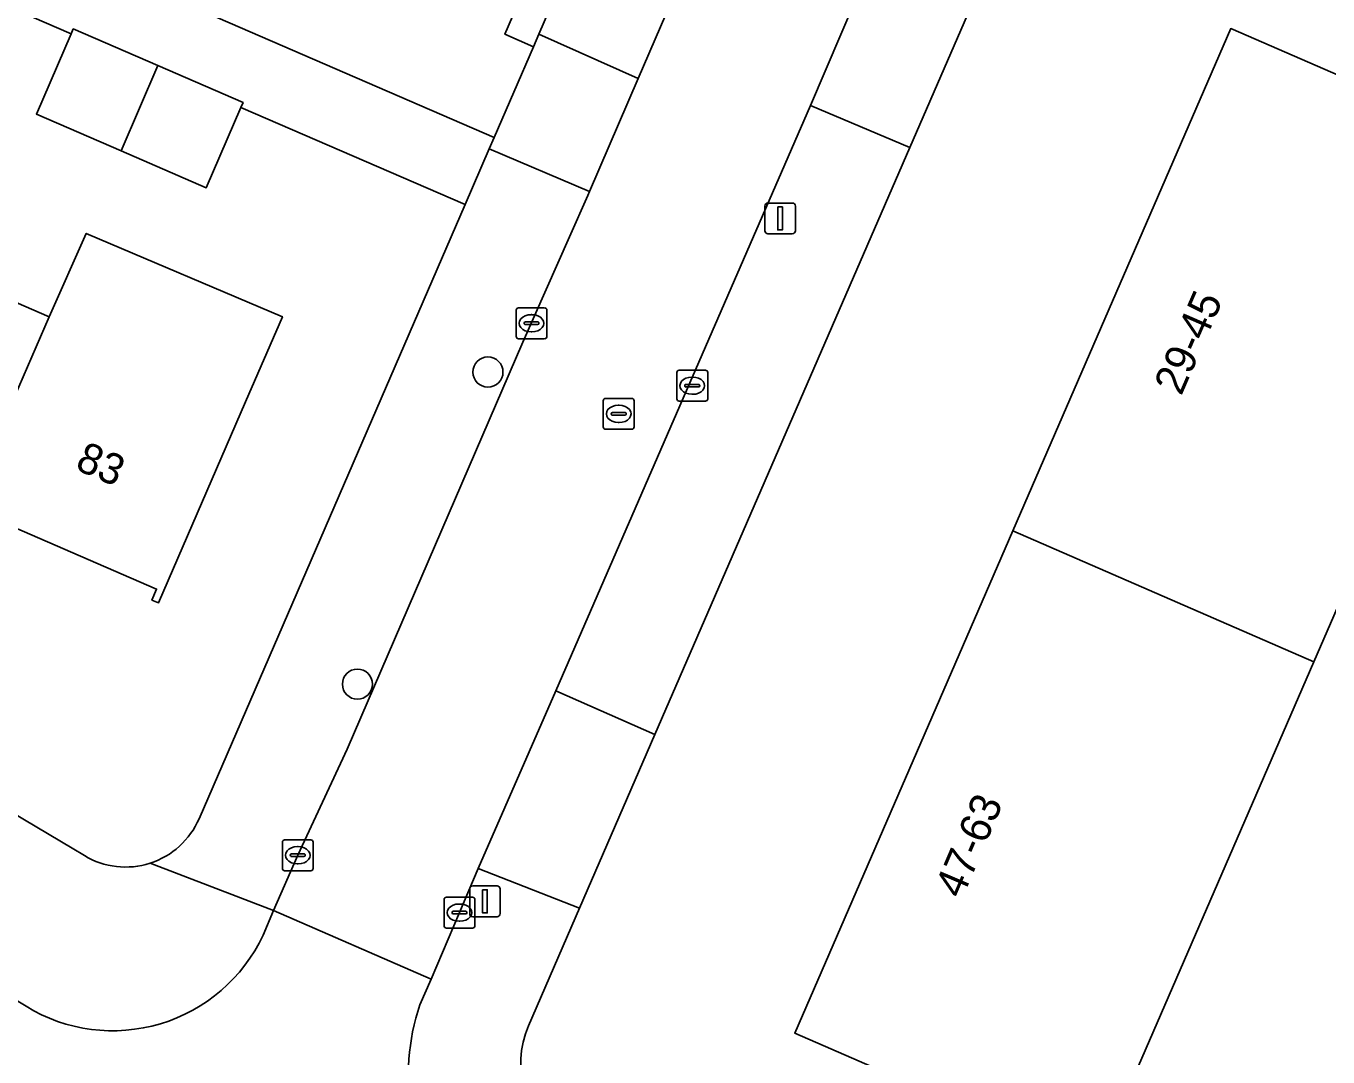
# Model space of a CAD drawing. Extents: x 162803 to 163818, y 381639 to 382475.
# Drawn here: x 163434.73 to 163477.02, y 381804.92 to 381838.38 of the extents above; entities that cross this region are included whole.
import ezdxf

# ---------------------------------------------------------------- set-up
doc = ezdxf.new("R2010")
doc.units = 0
for name, color, linetype in [('IMGEO_Boom', 7, 'Continuous'), ('IMGEO_Erf', 7, 'Continuous'), ('IMGEO_Groenvoorziening', 7, 'Continuous'), ('IMGEO_Kolk', 7, 'Continuous'), ('IMGEO_Lichtmast', 7, 'Continuous'), ('IMGEO_Pand', 7, 'Continuous'), ('IMGEO_Pand_nummerreeks', 7, 'Continuous'), ('IMGEO_Rijbaan_lokaal_gesloten', 7, 'Continuous'), ('IMGEO_Rijbaan_lokaal_open', 7, 'Continuous'), ('IMGEO_Rioolput', 7, 'Continuous'), ('IMGEO_Voetpad_open', 7, 'Continuous')]:
    doc.layers.add(name, color=color, linetype=linetype)

msp = doc.modelspace()

# ---------------------------------------------------------------- linework, layer by layer
at = {"layer": 'IMGEO_Boom'}
for centre in [(163449.734, 381827.148), (163445.496, 381817.017)]:
    msp.add_circle(centre, 0.489, dxfattribs=at)
at = {"layer": 'IMGEO_Erf'}
for points in [[(163436.198, 381838.123), (163434.517, 381838.854), (163432.723, 381839.632), (163429.378, 381841.081), (163428.109, 381838.155), (163425.245, 381839.398), (163425.173, 381839.429), (163422.236, 381840.702), (163423.504, 381843.626), (163420.299, 381845.015), (163413.989, 381847.548), (163416.807, 381846.326), (163415.568, 381843.47), (163412.751, 381844.692), (163412.199, 381843.419), (163405.84, 381846.176), (163407.63, 381850.305), (163403.019, 381852.311), (163395.819, 381835.705), (163436.629, 381811.45)], [(163467.165, 381843.034), (163465.988, 381840.322), (163463.432, 381834.438), (163455.158, 381815.381), (163452.711, 381809.747), (163451.053, 381805.927)], [(163440.352, 381812.65), (163448.992, 381832.592), (163441.712, 381835.735), (163440.584, 381833.133), (163437.818, 381834.332), (163435.07, 381835.523), (163436.198, 381838.123)], [(163429.266, 381831.638), (163435.482, 381828.943), (163436.691, 381831.651), (163443.06, 381828.944), (163441.861, 381826.178), (163439.032, 381819.653), (163438.82, 381819.745), (163438.975, 381820.104), (163432.952, 381822.703)]]:
    msp.add_lwpolyline(points, dxfattribs=at)
msp.add_lwpolyline([(163469.482, 381801.434), (163459.697, 381805.683), (163466.777, 381821.989), (163473.858, 381838.296), (163483.642, 381834.047), (163476.562, 381817.741)], close=True, dxfattribs=at)
for centre, radius, start, end in [((163437.966, 381813.676), 2.597, 287.8731, 336.7317), ((163437.967, 381813.675), 2.596, 238.9884, 287.8599), ((163453.778, 381804.734), 2.975, 156.3447, 240.6795)]:
    msp.add_arc(centre, radius, start, end, dxfattribs=at)
at = {"layer": 'IMGEO_Groenvoorziening'}
for points in [[(163455.817, 381848.343), (163454.888, 381848.734), (163454.325, 381847.435), (163450.286, 381838.112), (163451.209, 381837.708), (163451.387, 381838.119)], [(163435.32, 381840.713), (163434.517, 381838.854), (163436.198, 381838.123), (163436.268, 381838.286), (163439.015, 381837.095), (163441.782, 381835.896), (163441.712, 381835.735), (163448.992, 381832.592), (163449.775, 381834.399), (163449.934, 381834.765), (163435.46, 381841.037)]]:
    msp.add_lwpolyline(points, close=True, dxfattribs=at)
at = {"layer": 'IMGEO_Kolk'}
for p, q in [((163450.65, 381828.305), (163450.65, 381829.157)), ((163450.725, 381829.231), (163451.577, 381829.231)), ((163451.651, 381829.157), (163451.651, 381828.305)), ((163450.909, 381828.725), (163450.909, 381828.737)), ((163450.952, 381828.774), (163451.35, 381828.774)), ((163451.138, 381829.011), (163451.163, 381829.011)), ((163451.393, 381828.737), (163451.393, 381828.725)), ((163451.347, 381828.688), (163450.949, 381828.688)), ((163451.161, 381828.451), (163451.136, 381828.451)), ((163451.577, 381828.231), (163450.725, 381828.231)), ((163455.87, 381826.28), (163455.87, 381827.132)), ((163455.945, 381827.206), (163456.797, 381827.206)), ((163456.871, 381827.132), (163456.871, 381826.28)), ((163456.129, 381826.7), (163456.129, 381826.712)), ((163456.567, 381826.663), (163456.169, 381826.663)), ((163456.172, 381826.749), (163456.57, 381826.749)), ((163456.358, 381826.986), (163456.383, 381826.986)), ((163456.613, 381826.712), (163456.613, 381826.7)), ((163456.797, 381826.206), (163455.945, 381826.206)), ((163456.381, 381826.426), (163456.356, 381826.426)), ((163443.058, 381811.036), (163443.058, 381811.888)), ((163443.133, 381811.962), (163443.985, 381811.962)), ((163444.059, 381811.888), (163444.059, 381811.036)), ((163443.317, 381811.456), (163443.317, 381811.468)), ((163443.755, 381811.419), (163443.357, 381811.419)), ((163443.36, 381811.505), (163443.758, 381811.505)), ((163443.546, 381811.742), (163443.571, 381811.742)), ((163443.801, 381811.468), (163443.801, 381811.456)), ((163443.985, 381810.962), (163443.133, 381810.962)), ((163443.569, 381811.182), (163443.544, 381811.182)), ((163448.385, 381810.1), (163449.237, 381810.1)), ((163448.31, 381809.174), (163448.31, 381810.026)), ((163448.798, 381809.88), (163448.823, 381809.88)), ((163449.311, 381810.026), (163449.311, 381809.174)), ((163448.569, 381809.594), (163448.569, 381809.606)), ((163449.007, 381809.557), (163448.609, 381809.557)), ((163448.612, 381809.643), (163449.01, 381809.643)), ((163448.821, 381809.32), (163448.796, 381809.32)), ((163449.053, 381809.606), (163449.053, 381809.594)), ((163449.237, 381809.1), (163448.385, 381809.1))]:
    msp.add_line(p, q, dxfattribs=at)
for points in [[(163450.65, 381828.305), (163450.65, 381829.157)], [(163450.725, 381829.231), (163451.577, 381829.231)], [(163451.651, 381829.157), (163451.651, 381828.305)], [(163451.577, 381828.231), (163450.725, 381828.231)], [(163455.87, 381826.28), (163455.87, 381827.132)], [(163455.945, 381827.206), (163456.797, 381827.206)], [(163456.871, 381827.132), (163456.871, 381826.28)], [(163456.797, 381826.206), (163455.945, 381826.206)], [(163443.058, 381811.036), (163443.058, 381811.888)], [(163443.133, 381811.962), (163443.985, 381811.962)], [(163444.059, 381811.888), (163444.059, 381811.036)], [(163443.985, 381810.962), (163443.133, 381810.962)], [(163448.385, 381810.1), (163449.237, 381810.1)], [(163448.31, 381809.174), (163448.31, 381810.026)], [(163449.311, 381810.026), (163449.311, 381809.174)], [(163449.237, 381809.1), (163448.385, 381809.1)]]:
    msp.add_lwpolyline(points, dxfattribs=at)
for centre, radius, start, end in [((163450.727, 381829.155), 0.0765, 91.552, 178.448), ((163450.727, 381829.155), 0.0765, 91.552, 178.448), ((163451.575, 381829.155), 0.0765, 1.552, 88.448), ((163451.575, 381829.155), 0.0765, 1.552, 88.448), ((163450.949, 381828.734), 0.0403, 85.8775, 175.7526), ((163450.946, 381828.724), 0.0366, 178.938, 274.7102), ((163451.35, 381828.731), 0.043, 264.8664, 352.4533), ((163451.354, 381828.736), 0.0386, 1.7309, 96.639), ((163450.727, 381828.307), 0.0765, 181.552, 268.448), ((163450.727, 381828.307), 0.0765, 181.552, 268.448), ((163451.575, 381828.307), 0.0765, 271.552, 358.448), ((163451.575, 381828.307), 0.0765, 271.552, 358.448), ((163455.947, 381827.13), 0.0765, 91.552, 178.448), ((163455.947, 381827.13), 0.0765, 91.552, 178.448), ((163456.795, 381827.13), 0.0765, 1.552, 88.448), ((163456.795, 381827.13), 0.0765, 1.552, 88.448), ((163456.169, 381826.709), 0.0403, 85.8775, 175.7526), ((163456.166, 381826.699), 0.0366, 178.938, 274.7102), ((163456.57, 381826.706), 0.043, 264.8664, 352.4533), ((163456.574, 381826.711), 0.0386, 1.7309, 96.639), ((163455.947, 381826.282), 0.0765, 181.552, 268.448), ((163455.947, 381826.282), 0.0765, 181.552, 268.448), ((163456.795, 381826.282), 0.0765, 271.552, 358.448), ((163456.795, 381826.282), 0.0765, 271.552, 358.448), ((163443.135, 381811.886), 0.0765, 91.552, 178.448), ((163443.135, 381811.886), 0.0765, 91.552, 178.448), ((163443.983, 381811.886), 0.0765, 1.552, 88.448), ((163443.983, 381811.886), 0.0765, 1.552, 88.448), ((163443.357, 381811.465), 0.0403, 85.8775, 175.7526), ((163443.354, 381811.455), 0.0366, 178.938, 274.7102), ((163443.758, 381811.462), 0.043, 264.8664, 352.4533), ((163443.762, 381811.467), 0.0386, 1.7309, 96.639), ((163443.135, 381811.038), 0.0765, 181.552, 268.448), ((163443.135, 381811.038), 0.0765, 181.552, 268.448), ((163443.983, 381811.038), 0.0765, 271.552, 358.448), ((163443.983, 381811.038), 0.0765, 271.552, 358.448), ((163448.387, 381810.024), 0.0765, 91.552, 178.448), ((163448.387, 381810.024), 0.0765, 91.552, 178.448), ((163449.235, 381810.024), 0.0765, 1.552, 88.448), ((163449.235, 381810.024), 0.0765, 1.552, 88.448), ((163448.609, 381809.603), 0.0403, 85.8775, 175.7526), ((163448.606, 381809.593), 0.0366, 178.938, 274.7102), ((163449.01, 381809.6), 0.043, 264.8664, 352.4533), ((163449.014, 381809.605), 0.0386, 1.7309, 96.639), ((163448.387, 381809.176), 0.0765, 181.552, 268.448), ((163448.387, 381809.176), 0.0765, 181.552, 268.448), ((163449.235, 381809.176), 0.0765, 271.552, 358.448), ((163449.235, 381809.176), 0.0765, 271.552, 358.448)]:
    msp.add_arc(centre, radius, start, end, dxfattribs=at)
for centre, major_axis, ratio, start_param, end_param in [((163451.137, 381828.731), (-0.387, 0.002), 0.722429, 4.712389, 7.853982), ((163451.162, 381828.731), (-0.39, 0.002), 0.717154, 1.570796, 4.712389), ((163456.357, 381826.706), (-0.387, 0.002), 0.722429, 4.712389, 7.853982), ((163456.382, 381826.706), (-0.39, 0.002), 0.717154, 1.570796, 4.712389), ((163443.545, 381811.462), (-0.387, 0.002), 0.722429, 4.712389, 7.853982), ((163443.57, 381811.462), (-0.39, 0.002), 0.717154, 1.570796, 4.712389), ((163448.797, 381809.6), (-0.387, 0.002), 0.722429, 4.712389, 7.853982), ((163448.822, 381809.6), (-0.39, 0.002), 0.717154, 1.570796, 4.712389)]:
    msp.add_ellipse(centre, major_axis=major_axis, ratio=ratio, start_param=start_param, end_param=end_param, dxfattribs=at)
at = {"layer": 'IMGEO_Lichtmast'}
for p, q in [((163458.729, 381831.735), (163458.729, 381832.535)), ((163458.729, 381832.535), (163458.729, 381831.735)), ((163458.829, 381832.635), (163459.619, 381832.635)), ((163459.619, 381832.635), (163458.829, 381832.635)), ((163459.719, 381832.535), (163459.719, 381831.735)), ((163459.719, 381831.735), (163459.719, 381832.535)), ((163459.619, 381831.635), (163458.829, 381831.635)), ((163458.829, 381831.635), (163459.619, 381831.635)), ((163449.143, 381809.568), (163449.143, 381810.368)), ((163449.143, 381810.368), (163449.143, 381809.568)), ((163449.243, 381810.468), (163450.033, 381810.468)), ((163450.033, 381810.468), (163449.243, 381810.468)), ((163450.133, 381810.368), (163450.133, 381809.568)), ((163450.133, 381809.568), (163450.133, 381810.368)), ((163450.033, 381809.468), (163449.243, 381809.468)), ((163449.243, 381809.468), (163450.033, 381809.468))]:
    msp.add_line(p, q, dxfattribs=at)
for points in [[(163459.149, 381832.51), (163459.299, 381832.51), (163459.299, 381831.76), (163459.149, 381831.76), (163459.149, 381832.51)], [(163449.563, 381810.343), (163449.713, 381810.343), (163449.713, 381809.593), (163449.563, 381809.593), (163449.563, 381810.343)]]:
    msp.add_lwpolyline(points, dxfattribs=at)
for centre, start, end in [((163458.829, 381832.535), 90, 180), ((163458.829, 381832.535), 90, 180), ((163459.619, 381832.535), 0, 90), ((163459.619, 381832.535), 360, 90), ((163458.829, 381831.735), 180, 270), ((163458.829, 381831.735), 180, 270), ((163459.619, 381831.735), 270, 0), ((163459.619, 381831.735), 270, 0), ((163449.243, 381810.368), 90, 180), ((163449.243, 381810.368), 90, 180), ((163450.033, 381810.368), 0, 90), ((163450.033, 381810.368), 360, 90), ((163449.243, 381809.568), 180, 270), ((163449.243, 381809.568), 180, 270), ((163450.033, 381809.568), 270, 0), ((163450.033, 381809.568), 270, 0)]:
    msp.add_arc(centre, 0.1, start, end, dxfattribs=at)
at = {"layer": 'IMGEO_Pand'}
for points in [[(163439.015, 381837.095), (163436.268, 381838.286), (163436.198, 381838.123), (163435.07, 381835.523), (163437.818, 381834.332)], [(163466.777, 381821.989), (163476.562, 381817.741), (163483.642, 381834.047), (163473.858, 381838.296)], [(163441.712, 381835.735), (163441.782, 381835.896), (163439.015, 381837.095), (163437.818, 381834.332), (163440.584, 381833.133)], [(163435.482, 381828.943), (163429.266, 381831.638), (163426.44, 381825.116), (163426.587, 381825.052), (163426.732, 381825.387), (163432.658, 381822.83), (163432.518, 381822.507), (163432.665, 381822.443)], [(163441.861, 381826.178), (163443.06, 381828.944), (163436.691, 381831.651), (163435.482, 381828.943), (163432.665, 381822.443), (163432.812, 381822.379), (163432.952, 381822.703), (163438.975, 381820.104), (163438.82, 381819.745), (163439.032, 381819.653)], [(163466.777, 381821.989), (163459.697, 381805.683), (163469.482, 381801.434), (163476.562, 381817.741)]]:
    msp.add_lwpolyline(points, close=True, dxfattribs=at)
at = {"layer": 'IMGEO_Rijbaan_lokaal_gesloten'}
for points in [[(163447.527, 381806.61), (163447.896, 381807.44), (163442.774, 381809.67), (163442.431, 381808.864)], [(163434.734, 381806.559), (163433.645, 381807.215), (163432.06, 381804.479), (163441.867, 381798.366), (163449.899, 381794.075)]]:
    msp.add_lwpolyline(points, dxfattribs=at)
for centre, radius, start, end in [((163437.55, 381811.159), 5.393, 238.5245, 334.818), ((163454.105, 381804.368), 6.95, 161.18, 220.3026)]:
    msp.add_arc(centre, radius, start, end, dxfattribs=at)
at = {"layer": 'IMGEO_Rijbaan_lokaal_open'}
for points in [[(163462.723, 381841.684), (163464.217, 381845.074), (163469.867, 381858.162), (163476.868, 381874.378), (163471.893, 381876.637), (163454.618, 381836.679), (163453.03, 381833.006), (163452.976, 381832.881), (163452.381, 381831.536), (163450.868, 381828.115), (163445.164, 381814.911), (163443.559, 381811.462), (163442.774, 381809.67), (163447.896, 381807.44), (163448.811, 381809.6), (163449.421, 381811.034), (163451.945, 381816.796), (163460.206, 381835.802)], [(163454.325, 381847.435), (163450.186, 381849.176), (163448.068, 381844.29), (163445.202, 381845.532), (163442.337, 381846.775), (163439.471, 381848.017), (163436.605, 381849.259), (163433.704, 381842.563), (163432.128, 381842.14), (163435.32, 381840.713), (163435.46, 381841.037), (163449.934, 381834.765), (163451.209, 381837.708), (163450.286, 381838.112)]]:
    msp.add_lwpolyline(points, close=True, dxfattribs=at)
at = {"layer": 'IMGEO_Rioolput'}
for p, q in [((163453.481, 381825.365), (163453.481, 381826.217)), ((163453.556, 381826.291), (163454.408, 381826.291)), ((163454.482, 381826.217), (163454.482, 381825.365)), ((163453.74, 381825.785), (163453.74, 381825.797)), ((163454.178, 381825.748), (163453.78, 381825.748)), ((163453.783, 381825.834), (163454.181, 381825.834)), ((163453.969, 381826.071), (163453.994, 381826.071)), ((163454.224, 381825.797), (163454.224, 381825.785)), ((163453.992, 381825.511), (163453.967, 381825.511)), ((163454.408, 381825.291), (163453.556, 381825.291))]:
    msp.add_line(p, q, dxfattribs=at)
for points in [[(163453.481, 381825.365), (163453.481, 381826.217)], [(163453.556, 381826.291), (163454.408, 381826.291)], [(163454.482, 381826.217), (163454.482, 381825.365)], [(163454.408, 381825.291), (163453.556, 381825.291)]]:
    msp.add_lwpolyline(points, dxfattribs=at)
for centre, radius, start, end in [((163453.558, 381826.215), 0.0765, 91.552, 178.448), ((163453.558, 381826.215), 0.0765, 91.552, 178.448), ((163454.406, 381826.215), 0.0765, 1.552, 88.448), ((163454.406, 381826.215), 0.0765, 1.552, 88.448), ((163453.78, 381825.794), 0.0403, 85.8775, 175.7526), ((163453.777, 381825.784), 0.0366, 178.938, 274.7102), ((163454.181, 381825.791), 0.043, 264.8664, 352.4533), ((163454.185, 381825.796), 0.0386, 1.7309, 96.639), ((163453.558, 381825.367), 0.0765, 181.552, 268.448), ((163453.558, 381825.367), 0.0765, 181.552, 268.448), ((163454.406, 381825.367), 0.0765, 271.552, 358.448), ((163454.406, 381825.367), 0.0765, 271.552, 358.448)]:
    msp.add_arc(centre, radius, start, end, dxfattribs=at)
for centre, major_axis, ratio, start_param, end_param in [((163453.968, 381825.791), (-0.387, 0.002), 0.722429, 4.712389, 7.853982), ((163453.993, 381825.791), (-0.39, 0.002), 0.717154, 1.570796, 4.712389)]:
    msp.add_ellipse(centre, major_axis=major_axis, ratio=ratio, start_param=start_param, end_param=end_param, dxfattribs=at)
at = {"layer": 'IMGEO_Voetpad_open'}
for points in [[(163486.887, 381920.052), (163484.202, 381913.856), (163480.407, 381905.096), (163479.77, 381903.625), (163455.817, 381848.343), (163451.387, 381838.119), (163454.618, 381836.679), (163471.893, 381876.637)], [(163436.629, 381811.45), (163395.819, 381835.705), (163392.292, 381837.534), (163389.72, 381833.25), (163392.489, 381831.604), (163395.459, 381829.836), (163396.691, 381829.107), (163397.779, 381830.986), (163399.575, 381829.895), (163399.682, 381829.584)], [(163450.868, 381828.115), (163452.381, 381831.536), (163452.976, 381832.881), (163453.03, 381833.006), (163449.775, 381834.399), (163448.992, 381832.592), (163440.352, 381812.65)], [(163438.763, 381811.204), (163442.774, 381809.67), (163443.559, 381811.462), (163445.164, 381814.911), (163450.868, 381828.115)], [(163442.774, 381809.67), (163438.763, 381811.204)], [(163452.711, 381809.747), (163449.421, 381811.034), (163448.811, 381809.6), (163447.896, 381807.44), (163447.527, 381806.61)], [(163431.812, 381810.474), (163432.139, 381810.578), (163434.015, 381809.443), (163432.917, 381807.601), (163433.645, 381807.215), (163434.734, 381806.559)], [(163442.431, 381808.864), (163442.774, 381809.67)], [(163451.053, 381805.927), (163452.711, 381809.747)]]:
    msp.add_lwpolyline(points, dxfattribs=at)
for points in [[(163465.988, 381840.322), (163462.723, 381841.684), (163460.206, 381835.802), (163463.432, 381834.438)], [(163454.618, 381836.679), (163451.387, 381838.119), (163451.209, 381837.708), (163449.934, 381834.765), (163449.775, 381834.399), (163453.03, 381833.006)], [(163463.432, 381834.438), (163460.206, 381835.802), (163451.945, 381816.796), (163455.158, 381815.381)], [(163455.158, 381815.381), (163451.945, 381816.796), (163449.421, 381811.034), (163452.711, 381809.747)]]:
    msp.add_lwpolyline(points, close=True, dxfattribs=at)
for centre, radius, start, end in [((163437.966, 381813.676), 2.597, 287.8731, 336.7317), ((163437.967, 381813.675), 2.596, 238.9884, 287.8599), ((163437.55, 381811.159), 5.393, 238.5245, 334.818), ((163454.105, 381804.368), 6.95, 161.18, 220.3026), ((163453.778, 381804.734), 2.975, 156.3447, 240.6795)]:
    msp.add_arc(centre, radius, start, end, dxfattribs=at)

# ---------------------------------------------------------------- texts
at = {"layer": 'IMGEO_Pand_nummerreeks'}
for s, rotation, p in [('29-45', 66.5014, (163472.25, 381826.352)), ('83', 336.6577, (163436.29, 381824.006)), ('47-63', 66.8844, (163465.132, 381810.017))]:
    msp.add_text(s, height=1, rotation=rotation, dxfattribs=at).set_placement(p)

doc.saveas('drawing.dxf')
